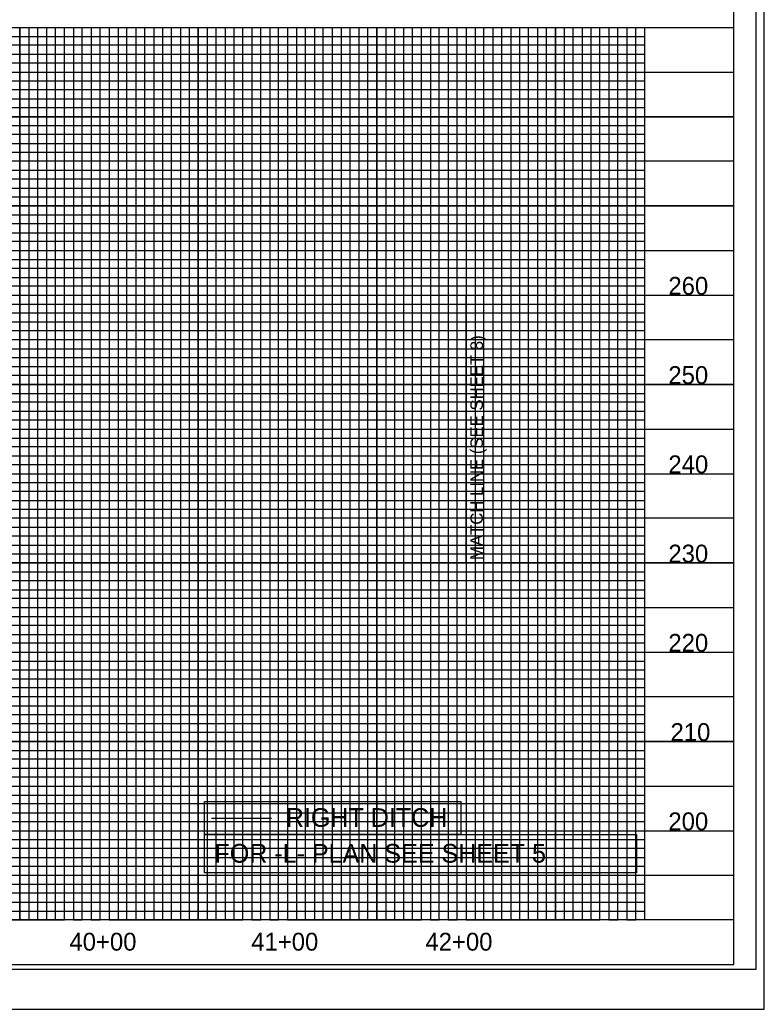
# Model space of a CAD drawing. Extents: x 1810963 to 1812948, y 722070 to 723250.
# Drawn here: x 1812230 to 1812647, y 722070 to 722624 of the extents above; entities that cross this region are included whole.
import ezdxf

# ---------------------------------------------------------------- set-up
doc = ezdxf.new("R2010")
doc.units = 0
for name, color, linetype in [('Exist Vertical Profile Horizontal Axis Label Major', 7, 'Continuous'), ('Exist Vertical Profile Vertical Axis Label', 7, 'Continuous'), ('Prop Grid Mask', 7, 'Continuous'), ('Prop Horizontal Alignment Station Label', 7, 'Continuous'), ('Prop Vertical Profile Ditch Grade Right', 7, 'Continuous'), ('Prop VPI Label', 7, 'Continuous'), ('Sheet Cutting Line CELL', 7, 'Continuous'), ('Sheet DOT Grid CELL', 7, 'Continuous'), ('Sheet Layout Profile Border Port 2', 7, 'Continuous'), ('Sheet Plot Border Inside CELL', 7, 'Continuous'), ('Sheet Plot Border Outside CELL', 7, 'Continuous'), ('Sheet Profile CELL', 7, 'Continuous'), ('Sheet Profile Grid Major CELL', 7, 'Continuous'), ('Sheet Profile Grid Middle CELL', 7, 'Continuous'), ('Sheet Profile Grid Minor CELL', 7, 'Continuous')]:
    doc.layers.add(name, color=color, linetype=linetype)

msp = doc.modelspace()

# ---------------------------------------------------------------- linework, layer by layer
at = {"layer": 'Prop Grid Mask'}
for points in [[(1812333.87, 722186.27), (1812477.53, 722186.27), (1812477.53, 722167.79), (1812333.87, 722167.79)], [(1812333.87, 722167.79), (1812575.88, 722167.79), (1812575.88, 722146.27), (1812333.87, 722146.27)]]:
    msp.add_lwpolyline(points, close=True, dxfattribs=at)
at = {"layer": 'Prop Vertical Profile Ditch Grade Right'}
msp.add_line((1812337.78, 722176.97), (1812371.42, 722176.97), dxfattribs=at)
at = {"layer": 'Prop VPI Label'}
msp.add_line((1812480.46, 722319.88), (1812480.46, 722469.88), dxfattribs=at)
at = {"layer": 'Sheet Cutting Line CELL'}
msp.add_line((1810963.46, 722069.88), (1812647.46, 722069.88), dxfattribs=at)
at = {"layer": 'Sheet DOT Grid CELL'}
for p, q in [((1811130.46, 722619.88), (1812630.35, 722619.88)), ((1812230.46, 722619.88), (1812230.46, 722119.88)), ((1812280.46, 722619.88), (1812280.46, 722119.88)), ((1812330.46, 722619.88), (1812330.46, 722119.88)), ((1812380.46, 722619.88), (1812380.46, 722119.88)), ((1812430.46, 722619.88), (1812430.46, 722119.88)), ((1812480.46, 722619.88), (1812480.46, 722119.88)), ((1812530.46, 722619.88), (1812530.46, 722119.88)), ((1812580.46, 722619.88), (1812580.46, 722119.88)), ((1811130.46, 722569.88), (1812630.35, 722569.88)), ((1811130.46, 722519.88), (1812630.35, 722519.88)), ((1811130.46, 722469.88), (1812630.35, 722469.88)), ((1811130.46, 722419.88), (1812630.35, 722419.88)), ((1811130.46, 722369.88), (1812630.35, 722369.88)), ((1811130.46, 722319.88), (1812630.35, 722319.88)), ((1811130.46, 722269.88), (1812630.35, 722269.88)), ((1811130.46, 722219.88), (1812630.35, 722219.88)), ((1811130.46, 722169.88), (1812630.35, 722169.88))]:
    msp.add_line(p, q, dxfattribs=at)
at = {"layer": 'Sheet Layout Profile Border Port 2'}
msp.add_lwpolyline([(1811180.46, 722619.88), (1812580.46, 722619.88), (1812580.46, 722119.88), (1811180.46, 722119.88)], close=True, dxfattribs=at)
at = {"layer": 'Sheet Plot Border Inside CELL'}
msp.add_lwpolyline([(1810976.46, 722092.33), (1812642.96, 722092.33), (1812642.96, 723147.43), (1810976.46, 723147.43)], close=True, dxfattribs=at)
at = {"layer": 'Sheet Plot Border Outside CELL'}
msp.add_lwpolyline([(1810963.46, 722069.88), (1812647.46, 722069.88), (1812647.46, 723169.88), (1810963.46, 723169.88)], close=True, dxfattribs=at)
at = {"layer": 'Sheet Profile CELL'}
for p, q in [((1811130.46, 722619.88), (1812630.46, 722619.88)), ((1812630.46, 722119.88), (1811130.46, 722119.88)), ((1811130.46, 722094.88), (1812630.46, 722094.88))]:
    msp.add_line(p, q, dxfattribs=at)
msp.add_lwpolyline([(1812630.46, 723144.88), (1811130.46, 723144.88), (1811130.46, 722094.88), (1812630.46, 722094.88)], close=True, dxfattribs=at)
at = {"layer": 'Sheet Profile Grid Major CELL'}
for p, q in [((1812230.46, 722619.88), (1812280.46, 722619.88)), ((1812330.46, 722619.88), (1812380.46, 722619.88)), ((1812430.46, 722619.88), (1812480.46, 722619.88)), ((1812530.46, 722619.88), (1812580.46, 722619.88)), ((1812530.46, 722119.88), (1812530.46, 722119.88))]:
    msp.add_line(p, q, dxfattribs=at)
for points in [[(1812180.46, 722119.88), (1812230.46, 722119.88), (1812230.46, 722619.88), (1812280.46, 722619.88), (1812280.46, 722119.88), (1812330.46, 722119.88), (1812330.46, 722619.88), (1812380.46, 722619.88), (1812380.46, 722119.88), (1812430.46, 722119.88), (1812430.46, 722619.88), (1812480.46, 722619.88), (1812480.46, 722119.88), (1812530.46, 722119.88), (1812530.46, 722119.88), (1812530.46, 722619.88), (1812580.46, 722619.88), (1812580.46, 722119.88)], [(1812630.46, 722569.88), (1811130.46, 722569.88)], [(1812630.46, 722519.88), (1811130.46, 722519.88), (1811130.46, 722469.88), (1812630.46, 722469.88)], [(1812630.46, 722419.88), (1811130.46, 722419.88), (1811130.46, 722369.88), (1812630.46, 722369.88)], [(1812630.46, 722319.88), (1811130.46, 722319.88), (1811130.46, 722269.88), (1812630.46, 722269.88)], [(1812630.46, 722219.88), (1811130.46, 722219.88), (1811130.46, 722219.88), (1811130.46, 722169.88), (1812630.46, 722169.88)], [(1812630.46, 722119.88), (1811130.46, 722119.88)]]:
    msp.add_lwpolyline(points, dxfattribs=at)
at = {"layer": 'Sheet Profile Grid Middle CELL'}
for points in [[(1812205.46, 722119.88), (1812255.46, 722119.88), (1812255.46, 722619.88), (1812305.46, 722619.88), (1812305.46, 722119.88), (1812355.46, 722119.88), (1812355.46, 722619.88), (1812405.46, 722619.88), (1812405.46, 722119.88), (1812455.46, 722119.88), (1812455.46, 722619.88), (1812505.46, 722619.88), (1812505.46, 722119.88), (1812555.46, 722119.88), (1812555.46, 722619.88)], [(1811130.46, 722594.88), (1812630.46, 722594.88)], [(1812630.46, 722544.88), (1811130.46, 722544.88), (1811130.46, 722494.88), (1812630.46, 722494.88)], [(1812630.46, 722444.88), (1811130.46, 722444.88), (1811130.46, 722394.88), (1812630.46, 722394.88)], [(1812630.46, 722344.88), (1811130.46, 722344.88), (1811130.46, 722294.88), (1812630.46, 722294.88)], [(1812630.46, 722244.88), (1811130.46, 722244.88), (1811130.46, 722194.88), (1812630.46, 722194.88)], [(1812630.46, 722144.88), (1811130.46, 722144.88)]]:
    msp.add_lwpolyline(points, dxfattribs=at)
at = {"layer": 'Sheet Profile Grid Minor CELL'}
for p, q in [((1811180.46, 722614.88), (1812580.46, 722614.88)), ((1812580.46, 722609.88), (1811180.46, 722609.88)), ((1811180.46, 722604.88), (1812580.46, 722604.88)), ((1812580.46, 722599.88), (1811180.46, 722599.88)), ((1811180.46, 722589.88), (1812580.46, 722589.88)), ((1812580.46, 722584.88), (1811180.46, 722584.88)), ((1811180.46, 722579.88), (1812580.46, 722579.88)), ((1812580.46, 722574.88), (1811180.46, 722574.88)), ((1811180.46, 722564.88), (1812580.46, 722564.88)), ((1812580.46, 722559.88), (1811180.46, 722559.88)), ((1811180.46, 722554.88), (1812580.46, 722554.88)), ((1812580.46, 722549.88), (1811180.46, 722549.88)), ((1811180.46, 722539.88), (1812580.46, 722539.88)), ((1812580.46, 722534.88), (1811180.46, 722534.88)), ((1811180.46, 722529.88), (1812580.46, 722529.88)), ((1812580.46, 722524.88), (1811180.46, 722524.88)), ((1811180.46, 722514.88), (1812580.46, 722514.88)), ((1812580.46, 722509.88), (1811180.46, 722509.88)), ((1811180.46, 722504.88), (1812580.46, 722504.88)), ((1812580.46, 722499.88), (1811180.46, 722499.88)), ((1811180.46, 722489.88), (1812580.46, 722489.88)), ((1812580.46, 722484.88), (1811180.46, 722484.88)), ((1811180.46, 722479.88), (1812580.46, 722479.88)), ((1812580.46, 722474.88), (1811180.46, 722474.88)), ((1811180.46, 722464.88), (1812580.46, 722464.88)), ((1812580.46, 722459.88), (1811180.46, 722459.88)), ((1811180.46, 722454.88), (1812580.46, 722454.88)), ((1812580.46, 722449.88), (1811180.46, 722449.88)), ((1811180.46, 722439.88), (1812580.46, 722439.88)), ((1812580.46, 722434.88), (1811180.46, 722434.88)), ((1811180.46, 722429.88), (1812580.46, 722429.88)), ((1812580.46, 722424.88), (1811180.46, 722425.03)), ((1811180.46, 722414.88), (1812580.46, 722414.88)), ((1812580.46, 722409.88), (1811180.46, 722409.88)), ((1811180.46, 722404.88), (1812580.46, 722404.88)), ((1812580.46, 722399.88), (1811180.46, 722399.88)), ((1811180.46, 722389.88), (1812580.46, 722389.88)), ((1812580.46, 722384.88), (1811180.46, 722384.88)), ((1811180.46, 722379.88), (1812580.46, 722379.88)), ((1812580.46, 722374.88), (1811180.46, 722374.88)), ((1811180.46, 722364.88), (1812580.46, 722364.88)), ((1812580.46, 722359.88), (1811180.46, 722359.88)), ((1811180.46, 722354.88), (1812580.46, 722354.88)), ((1812580.46, 722349.88), (1811180.46, 722349.88)), ((1811180.46, 722339.88), (1812580.46, 722339.88)), ((1812580.46, 722334.88), (1811180.46, 722334.88)), ((1811180.46, 722329.88), (1812580.46, 722329.88)), ((1812580.46, 722324.88), (1811180.46, 722324.88)), ((1811180.46, 722314.88), (1812580.46, 722314.88)), ((1812580.46, 722309.88), (1811180.46, 722309.88)), ((1811180.46, 722304.88), (1812580.46, 722304.88)), ((1812580.46, 722299.88), (1811180.46, 722299.88)), ((1811180.46, 722289.88), (1812580.46, 722289.88)), ((1812580.46, 722284.88), (1811180.46, 722284.88)), ((1811180.46, 722279.88), (1812580.46, 722279.88)), ((1812580.46, 722274.88), (1811180.46, 722274.88)), ((1811180.46, 722264.88), (1812580.46, 722264.88)), ((1812580.46, 722259.88), (1811180.46, 722259.88)), ((1811180.46, 722254.88), (1812580.46, 722254.88)), ((1812580.46, 722249.88), (1811180.46, 722249.88)), ((1811180.46, 722239.88), (1812580.46, 722239.88)), ((1812580.46, 722234.88), (1811180.46, 722234.88)), ((1811180.46, 722229.88), (1812580.46, 722229.88)), ((1812580.46, 722224.88), (1811180.46, 722224.88)), ((1811180.46, 722214.88), (1812580.46, 722214.88)), ((1812580.46, 722209.88), (1811180.46, 722209.88)), ((1811180.46, 722204.88), (1812580.46, 722204.88)), ((1812580.46, 722199.88), (1811180.46, 722199.88)), ((1811180.46, 722189.88), (1812580.46, 722189.88)), ((1812580.46, 722184.88), (1811180.46, 722184.88)), ((1811180.46, 722179.88), (1812580.46, 722179.88)), ((1812580.46, 722174.88), (1811180.46, 722174.88)), ((1811180.46, 722164.88), (1812580.46, 722164.88)), ((1812580.46, 722159.88), (1811180.46, 722159.88)), ((1811180.46, 722154.88), (1812580.46, 722154.88)), ((1812580.46, 722149.88), (1811180.46, 722149.88)), ((1811180.46, 722139.88), (1812580.46, 722139.88)), ((1812580.46, 722134.88), (1811180.46, 722134.88)), ((1811180.46, 722129.88), (1812580.46, 722129.88)), ((1811180.46, 722124.88), (1812580.46, 722124.88)), ((1812580.46, 722124.88), (1812580.46, 722124.88))]:
    msp.add_line(p, q, dxfattribs=at)
for points in [[(1812225.46, 722619.88), (1812235.46, 722619.88), (1812235.46, 722119.88), (1812240.46, 722119.88), (1812240.46, 722619.88), (1812245.46, 722619.88), (1812245.46, 722119.88), (1812250.46, 722119.88), (1812250.46, 722619.88), (1812260.46, 722619.88), (1812260.46, 722119.88), (1812265.46, 722119.88), (1812265.46, 722619.88), (1812270.46, 722619.88), (1812270.46, 722119.88), (1812275.46, 722119.88), (1812275.46, 722619.88), (1812285.46, 722619.88), (1812285.46, 722119.88), (1812290.46, 722119.88), (1812290.46, 722619.88), (1812295.46, 722619.88), (1812295.46, 722119.88), (1812300.46, 722119.88), (1812300.46, 722619.88), (1812310.46, 722619.88), (1812310.46, 722119.88), (1812315.46, 722119.88), (1812315.46, 722619.88), (1812320.46, 722619.88), (1812320.46, 722119.88)], [(1812320.46, 722119.88), (1812325.46, 722119.88), (1812325.46, 722619.88), (1812335.46, 722619.88), (1812335.46, 722119.88), (1812340.46, 722119.88), (1812340.46, 722619.88), (1812345.46, 722619.88), (1812345.46, 722119.88), (1812350.46, 722119.88), (1812350.46, 722619.88), (1812360.46, 722619.88), (1812360.46, 722119.88), (1812365.46, 722119.88), (1812365.46, 722619.88), (1812370.46, 722619.88), (1812370.46, 722119.88), (1812375.46, 722119.88), (1812375.46, 722619.88), (1812385.46, 722619.88), (1812385.46, 722119.88), (1812390.46, 722119.88), (1812390.46, 722619.88), (1812395.46, 722619.88), (1812395.46, 722119.88), (1812400.46, 722119.88), (1812400.46, 722619.88), (1812410.46, 722619.88), (1812410.46, 722119.88), (1812415.46, 722119.88), (1812415.46, 722619.88), (1812420.46, 722619.88), (1812420.46, 722119.88), (1812425.46, 722119.88), (1812425.46, 722619.88), (1812435.46, 722619.88), (1812435.46, 722119.88), (1812440.46, 722119.88), (1812440.46, 722619.88), (1812445.46, 722619.88), (1812445.46, 722119.88), (1812450.46, 722119.88), (1812450.46, 722619.88), (1812460.46, 722619.88), (1812460.46, 722119.88), (1812465.46, 722119.88), (1812465.46, 722619.88), (1812470.46, 722619.88), (1812470.46, 722119.88), (1812475.46, 722119.88), (1812475.46, 722619.88), (1812485.46, 722619.88), (1812485.46, 722119.88), (1812490.46, 722119.88), (1812490.46, 722619.88), (1812495.46, 722619.88), (1812495.46, 722119.88), (1812500.46, 722119.88), (1812500.46, 722619.88), (1812510.46, 722619.88), (1812510.46, 722119.88), (1812515.46, 722119.88), (1812515.46, 722619.88), (1812520.46, 722619.88), (1812520.46, 722119.88), (1812525.46, 722119.88), (1812525.46, 722619.88), (1812535.46, 722619.88), (1812535.46, 722119.88), (1812540.46, 722119.88), (1812540.46, 722619.88), (1812545.46, 722619.88), (1812545.46, 722119.88), (1812550.46, 722119.88), (1812550.46, 722619.88), (1812560.46, 722619.88), (1812560.46, 722119.88), (1812565.46, 722119.88), (1812565.46, 722619.88), (1812570.46, 722619.88), (1812570.46, 722119.88), (1812575.46, 722119.88), (1812575.46, 722619.88), (1812580.46, 722619.88)]]:
    msp.add_lwpolyline(points, dxfattribs=at)

# ---------------------------------------------------------------- texts
at = {"layer": 'Exist Vertical Profile Horizontal Axis Label Major'}
for s, p in [('40+00', (1812258.26, 722102.7)), ('41+00', (1812360.1, 722102.7)), ('42+00', (1812457.68, 722102.7))]:
    msp.add_text(s, height=10, dxfattribs=at).set_placement(p)
at = {"layer": 'Exist Vertical Profile Vertical Axis Label'}
for s, p in [('260', (1812593.78, 722470.13)), ('250', (1812593.78, 722420.13)), ('240', (1812593.78, 722370.13)), ('230', (1812593.78, 722320.13)), ('220', (1812593.78, 722270.13)), ('210', (1812594.98, 722220.13)), ('200', (1812593.78, 722170.13))]:
    msp.add_text(s, height=10, dxfattribs=at).set_placement(p)
at = {"layer": 'Prop Horizontal Alignment Station Label'}
for s, p in [('RIGHT DITCH', (1812379.47, 722172.03)), ('FOR -L- PLAN SEE SHEET 5', (1812339.5, 722151.98))]:
    msp.add_text(s, height=10.5, rotation=360, dxfattribs=at).set_placement(p)
at = {"layer": 'Prop VPI Label'}
msp.add_text('MATCH LINE (SEE SHEET 8)', height=7, rotation=90, dxfattribs=at).set_placement((1812489.88, 722321.54))

doc.saveas('drawing.dxf')
